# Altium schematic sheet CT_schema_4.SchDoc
size 145 x 123 mm
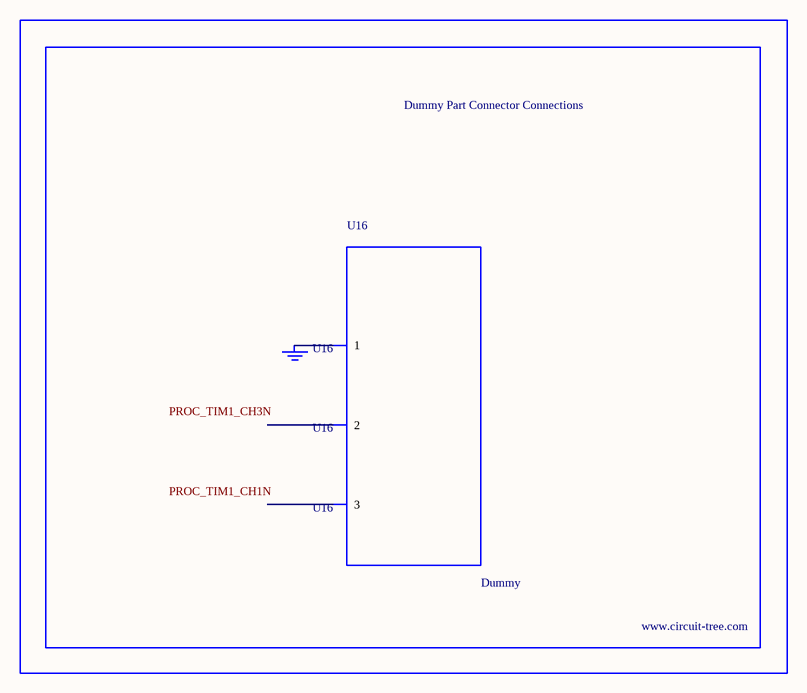
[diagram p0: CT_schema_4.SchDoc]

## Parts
BORDER3  (no value)
GND_INSTANCE_3_0  (no value)
U16  Dummy  [DUMMY_PACKAGE_139]

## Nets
NetGND_INSTANCE_3_0_0: GND_INSTANCE_3_0.0(GND) U16.1

Not connected (* = marked no-connect by the designer): U16 2 3

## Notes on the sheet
- Labels drawn without touching a wire or pin: PROC_TIM1_CH1N, PROC_TIM1_CH3N

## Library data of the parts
BORDER3 = BORDER_PAGE3
GND_INSTANCE_3_0 = GND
